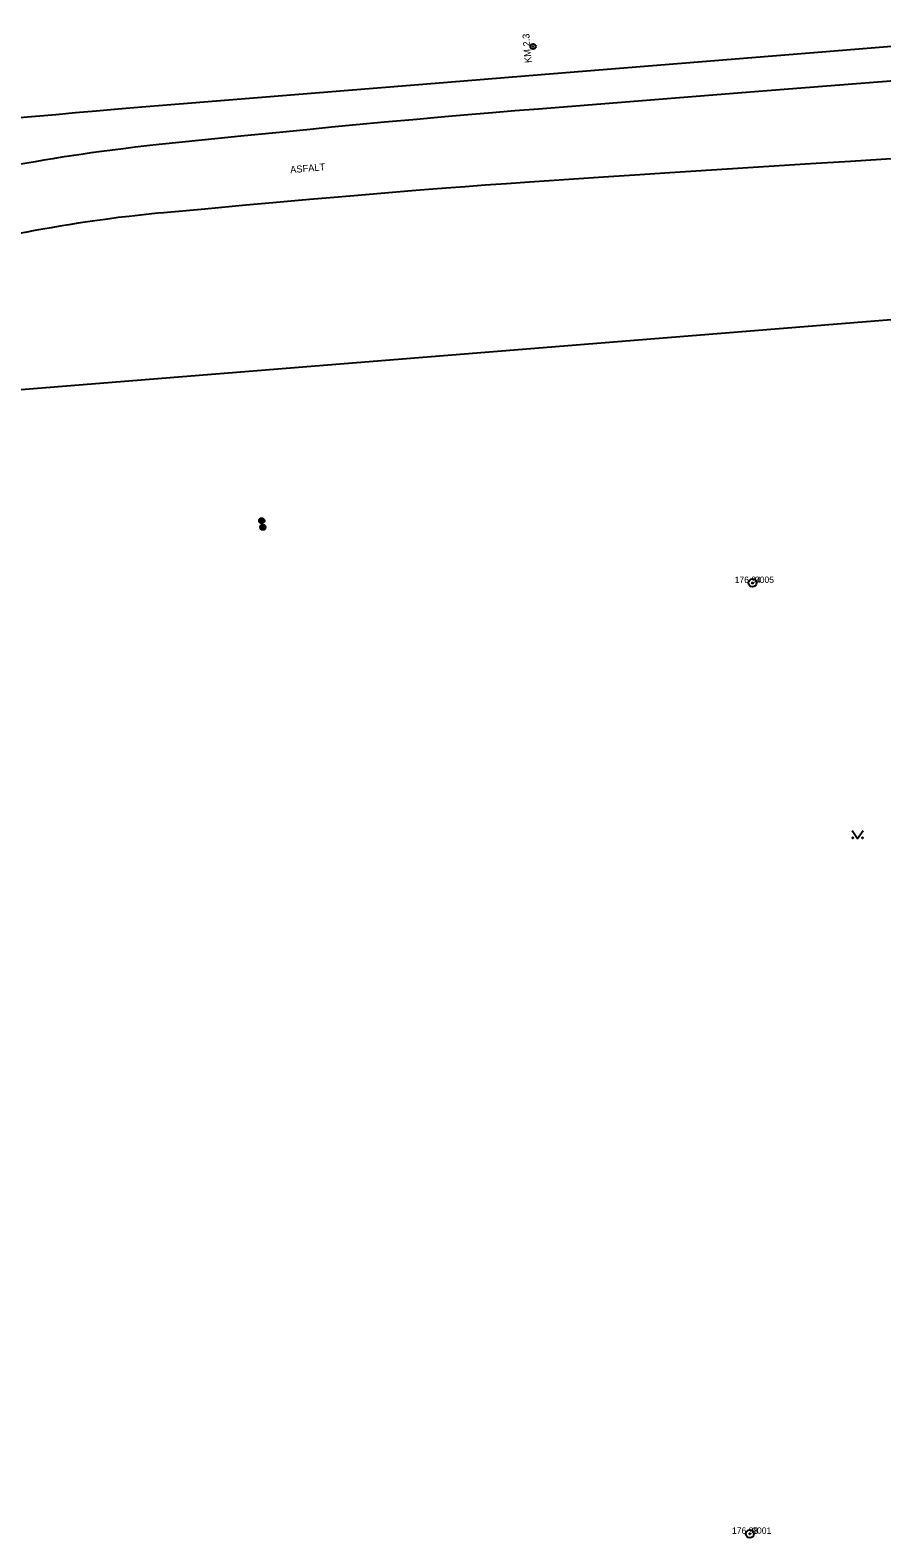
# Model space of a CAD drawing. Extents: x -541281 to -539153, y -1183881 to -1182141.
# Drawn here: x -539680.5 to -539600.8, y -1183307.5 to -1183166.3 of the extents above; entities that cross this region are included whole.
import ezdxf

# ---------------------------------------------------------------- set-up
doc = ezdxf.new("R2010")
doc.units = 0
for name, color, linetype in [('Vrstva 10', 7, 'Continuous'), ('Vrstva 13', 7, 'Continuous'), ('Vrstva 21', 7, 'Continuous'), ('Vrstva 22', 7, 'Continuous'), ('Vrstva 23', 7, 'Continuous'), ('Vrstva 25', 7, 'Continuous'), ('Vrstva 36', 7, 'Continuous'), ('Vrstva 40', 7, 'Continuous'), ('Vrstva 7', 7, 'Continuous')]:
    doc.layers.add(name, color=color, linetype=linetype)

msp = doc.modelspace()

# ---------------------------------------------------------------- linework, layer by layer
at = {"layer": 'Vrstva 10'}
for p, q in [((-539593.35, -1183170.59), (-539613.16, -1183172.15)), ((-539613.16, -1183172.15), (-539632.97, -1183173.72)), ((-539603.76, -1183178.62), (-539607.52, -1183178.86)), ((-539607.52, -1183178.86), (-539620.67, -1183179.69)), ((-539639.84, -1183181), (-539641.61, -1183181.13)), ((-539660.37, -1183182.73), (-539664.19, -1183183.08)), ((-539650.25, -1183181.84), (-539652.47, -1183182.03))]:
    msp.add_line(p, q, dxfattribs=at)
for points in [[(-539642.77, -1183174.54), (-539644.37, -1183174.69), (-539647.39, -1183174.96), (-539650.02, -1183175.21), (-539652.33, -1183175.43)], [(-539632.97, -1183173.72), (-539635.19, -1183173.9), (-539637.27, -1183174.07), (-539639.22, -1183174.24), (-539641.05, -1183174.39), (-539642.77, -1183174.54)], [(-539652.33, -1183175.43), (-539654.34, -1183175.62), (-539657.87, -1183175.97), (-539660.52, -1183176.23)], [(-539669.61, -1183177.17), (-539670.72, -1183177.3), (-539671.8, -1183177.43), (-539672.84, -1183177.56), (-539673.85, -1183177.7)], [(-539660.52, -1183176.23), (-539664.49, -1183176.64), (-539668.46, -1183177.05), (-539669.61, -1183177.17)], [(-539673.85, -1183177.7), (-539674.82, -1183177.83), (-539675.77, -1183177.97), (-539676.68, -1183178.1), (-539677.57, -1183178.24), (-539678.43, -1183178.38), (-539679.26, -1183178.51), (-539680.06, -1183178.65), (-539680.84, -1183178.78), (-539681.59, -1183178.91), (-539682.32, -1183179.04), (-539683.03, -1183179.17), (-539683.71, -1183179.3)], [(-539594.73, -1183178.03), (-539597.18, -1183178.19), (-539599.46, -1183178.35), (-539603.76, -1183178.62)], [(-539620.67, -1183179.69), (-539623.96, -1183179.9), (-539626.42, -1183180.06), (-539630.12, -1183180.31)], [(-539641.61, -1183181.13), (-539643.26, -1183181.26), (-539644.81, -1183181.39), (-539647.71, -1183181.63), (-539650.25, -1183181.84)], [(-539630.12, -1183180.31), (-539631.97, -1183180.43), (-539633.82, -1183180.56), (-539635.96, -1183180.71), (-539637.96, -1183180.86), (-539639.84, -1183181)], [(-539652.47, -1183182.03), (-539654.41, -1183182.2), (-539657.82, -1183182.5), (-539660.37, -1183182.73)], [(-539673.28, -1183184.02), (-539674.23, -1183184.15), (-539675.16, -1183184.28), (-539676.05, -1183184.42), (-539676.92, -1183184.55), (-539677.76, -1183184.69)], [(-539664.19, -1183183.08), (-539668.02, -1183183.43), (-539668.58, -1183183.48), (-539669.14, -1183183.54), (-539669.68, -1183183.59), (-539670.22, -1183183.65), (-539670.75, -1183183.71), (-539671.27, -1183183.77), (-539672.29, -1183183.89), (-539673.28, -1183184.02)], [(-539677.76, -1183184.69), (-539678.57, -1183184.83), (-539679.35, -1183184.96), (-539680.11, -1183185.1), (-539680.85, -1183185.24), (-539681.56, -1183185.37), (-539682.25, -1183185.51), (-539682.92, -1183185.64), (-539683.57, -1183185.77), (-539684.19, -1183185.9), (-539684.8, -1183186.03), (-539685.38, -1183186.16), (-539685.95, -1183186.28), (-539687.05, -1183186.53)]]:
    msp.add_lwpolyline(points, dxfattribs=at)
at = {"layer": 'Vrstva 13'}
for p, q in [((-539580.92, -1183166.33), (-539606.82, -1183168.42)), ((-539606.82, -1183168.42), (-539632.72, -1183170.51)), ((-539641.47, -1183171.22), (-539654.61, -1183172.29)), ((-539632.72, -1183170.51), (-539641.47, -1183171.22)), ((-539654.61, -1183172.29), (-539667.74, -1183173.36))]:
    msp.add_line(p, q, dxfattribs=at)
for points in [[(-539676.31, -1183174.08), (-539678.13, -1183174.25), (-539681.54, -1183174.55), (-539684.52, -1183174.83)], [(-539667.74, -1183173.36), (-539670.09, -1183173.55), (-539672.3, -1183173.74), (-539674.37, -1183173.92), (-539676.31, -1183174.08)]]:
    msp.add_lwpolyline(points, dxfattribs=at)
at = {"layer": 'Vrstva 21'}
for centre, radius in [((-539612.94, -1183218.1), 0.375), ((-539612.94, -1183218.1), 0.05), ((-539613.19, -1183307.15), 0.375), ((-539613.19, -1183307.15), 0.05)]:
    msp.add_circle(centre, radius, dxfattribs=at)
at = {"layer": 'Vrstva 25'}
for centre, radius in [((-539633.48, -1183167.86), 0.25), ((-539633.48, -1183167.86), 0.0303), ((-539658.87, -1183212.27), 0.25), ((-539658.87, -1183212.27), 0.2), ((-539658.87, -1183212.27), 0.15), ((-539658.77, -1183212.89), 0.25), ((-539658.87, -1183212.27), 0.1), ((-539658.87, -1183212.27), 0.05), ((-539658.77, -1183212.89), 0.2), ((-539658.77, -1183212.89), 0.15), ((-539658.77, -1183212.89), 0.1), ((-539658.77, -1183212.89), 0.05)]:
    msp.add_circle(centre, radius, dxfattribs=at)
at = {"layer": 'Vrstva 36'}
msp.add_lwpolyline([(-539603.6, -1183241.27), (-539603.1, -1183242.02), (-539602.6, -1183241.27)], dxfattribs=at)
for centre in [(-539603.55, -1183241.97), (-539602.65, -1183241.97)]:
    msp.add_circle(centre, 0.05, dxfattribs=at)
at = {"layer": 'Vrstva 7'}
for p, q in [((-539603.45, -1183193.7), (-539561.39, -1183190.29)), ((-539717.15, -1183202.86), (-539603.45, -1183193.7))]:
    msp.add_line(p, q, dxfattribs=at)

# ---------------------------------------------------------------- texts
at = {"layer": 'Vrstva 22'}
for s, p in [('176 94', (-539614.61, -1183218.1)), ('176 98', (-539614.86, -1183307.15))]:
    msp.add_text(s, height=0.6, dxfattribs=at).set_placement(p)
at = {"layer": 'Vrstva 23'}
for s, p in [(' 9005', (-539612.94, -1183218.1)), (' 9001', (-539613.19, -1183307.15))]:
    msp.add_text(s, height=0.6, dxfattribs=at).set_placement(p)
at = {"layer": 'Vrstva 40'}
for s, rotation, p in [('KM 2.3', 94.6179, (-539633.61, -1183169.38)), ('ASFALT', 5.023, (-539656.18, -1183179.73))]:
    msp.add_text(s, height=0.65, rotation=rotation, dxfattribs=at).set_placement(p)

doc.saveas('drawing.dxf')
